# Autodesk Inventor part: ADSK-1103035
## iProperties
Shininess: 50.0
Length Units: 11269
Angle Units: 11279
Time Units: 11290
Mass Units: 11286
Length Display Precision: 2
Angle Display Precision: 2
Compacted: True
Created: 2000-07
Part Number: ADSK-1103035
Document SubType Name: Modeling
Description: COMPRESSION BUTTON
Mass: 4.40676 g
Surface Area: 17.611 cm^2
Volume: 1.62611 cm^3
Density: 2.71 g/cm^3
Material: Aluminum-6061
Density: 0.0
Volumn: 0.0
Area: 0.0
PropertySet Name: Model Information
Control State: 0
Master: False
Checked Out: False
Author: Autodesk, Inc.
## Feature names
1. Hole1
2. Chamfer2
3. Hole2
4. Circular Pattern1
